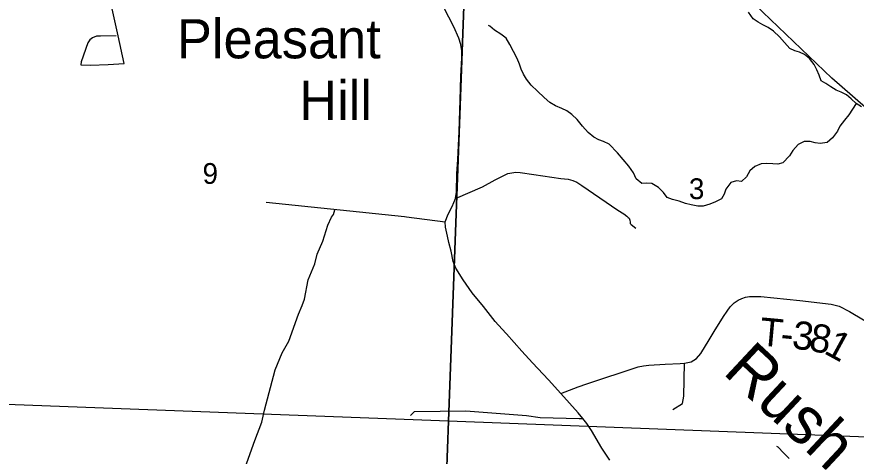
# Model space of a CAD drawing. Extents: x 0 to 34, y 0 to 22.
# Drawn here: x 4.552 to 6.245, y 15.005 to 15.891 of the extents above; entities that cross this region are included whole.
import ezdxf

# ---------------------------------------------------------------- set-up
doc = ezdxf.new("R2010")
doc.units = 0
for name, color, linetype in [('Default', 7, 'Continuous'), ('GM_X_Minor_River', 7, 'Continuous'), ('GM_X_Minor_River_Text', 7, 'Continuous'), ('GM_X_Section', 7, 'Continuous'), ('GM_X_Section_Text', 7, 'Continuous'), ('GM_X_State_Route', 7, 'Continuous'), ('GM_X_Township_Road', 7, 'Continuous'), ('GM_X_Township_Road_Text', 7, 'Continuous'), ('GM_X_Unincorporated_Text', 7, 'Continuous')]:
    doc.layers.add(name, color=color, linetype=linetype)

msp = doc.modelspace()

# ---------------------------------------------------------------- linework, layer by layer
at = {"layer": 'Default'}
for p, q in [((5.4229, 15.0756), (4.4256, 15.1132)), ((5.4229, 15.0756), (5.3878, 14.1)), ((5.3878, 14.1), (5.4229, 15.0756)), ((6.3944, 15.0386), (5.4229, 15.0756))]:
    msp.add_line(p, q, dxfattribs=at)
at = {"layer": 'GM_X_Minor_River'}
for p, q in [((6.037, 15.8876), (6.0279, 15.9006)), ((6.0472, 15.8803), (6.037, 15.8876)), ((6.0568, 15.8753), (6.0472, 15.8803)), ((5.506, 15.8725), (5.5033, 15.874)), ((5.5158, 15.8641), (5.506, 15.8725)), ((5.5282, 15.8561), (5.5158, 15.8641)), ((6.0676, 15.8699), (6.0568, 15.8753)), ((6.0785, 15.8622), (6.0676, 15.8699)), ((5.5391, 15.8485), (5.5282, 15.8561)), ((5.5467, 15.8354), (5.5391, 15.8485)), ((6.0903, 15.8512), (6.0785, 15.8622)), ((6.1005, 15.8393), (6.0903, 15.8512)), ((5.5536, 15.8211), (5.5467, 15.8354)), ((6.1112, 15.8275), (6.1005, 15.8393)), ((5.5609, 15.8073), (5.5536, 15.8211)), ((6.1212, 15.8229), (6.1112, 15.8275)), ((6.1308, 15.8201), (6.1212, 15.8229)), ((6.1408, 15.8155), (6.1308, 15.8201)), ((6.1506, 15.8071), (6.1408, 15.8155)), ((5.5658, 15.796), (5.5609, 15.8073)), ((5.5696, 15.7855), (5.5658, 15.796)), ((6.1601, 15.7952), (6.1506, 15.8071)), ((5.5737, 15.7757), (5.5696, 15.7855)), ((6.1657, 15.7847), (6.1601, 15.7952)), ((6.1702, 15.7738), (6.1657, 15.7847)), ((5.5797, 15.7656), (5.5737, 15.7757)), ((5.5896, 15.7538), (5.5797, 15.7656)), ((6.174, 15.7621), (6.1702, 15.7738)), ((6.1837, 15.7567), (6.174, 15.7621)), ((5.6021, 15.7412), (5.5896, 15.7538)), ((6.1938, 15.7502), (6.1837, 15.7567)), ((6.2046, 15.7437), (6.1938, 15.7502)), ((5.6158, 15.7284), (5.6021, 15.7412)), ((5.6268, 15.7188), (5.6158, 15.7284)), ((6.2146, 15.7395), (6.2046, 15.7437)), ((6.2251, 15.7341), (6.2146, 15.7395)), ((6.2348, 15.7256), (6.2251, 15.7341)), ((5.6388, 15.7116), (5.6268, 15.7188)), ((5.6515, 15.7066), (5.6388, 15.7116)), ((6.2446, 15.7168), (6.2298, 15.6939)), ((6.2446, 15.7168), (6.2348, 15.7256)), ((6.2555, 15.7099), (6.2446, 15.7168)), ((5.6615, 15.702), (5.6515, 15.7066)), ((5.6717, 15.694), (5.6615, 15.702)), ((5.6819, 15.684), (5.6717, 15.694)), ((5.6929, 15.671), (5.6819, 15.684)), ((6.2217, 15.683), (6.2119, 15.6705)), ((6.2298, 15.6939), (6.2217, 15.683)), ((5.7047, 15.6577), (5.6929, 15.671)), ((6.2072, 15.6605), (6.1974, 15.6472)), ((6.2119, 15.6705), (6.2072, 15.6605)), ((5.7157, 15.6485), (5.7047, 15.6577)), ((5.7257, 15.6435), (5.7157, 15.6485)), ((5.7353, 15.64), (5.7257, 15.6435)), ((6.1974, 15.6472), (6.1863, 15.6378)), ((5.7465, 15.6343), (5.7353, 15.64)), ((5.7638, 15.6173), (5.7465, 15.6343)), ((6.1282, 15.6337), (6.1172, 15.6215)), ((6.1398, 15.6401), (6.1282, 15.6337)), ((6.1524, 15.6401), (6.1398, 15.6401)), ((6.1623, 15.6374), (6.1524, 15.6401)), ((6.1726, 15.6358), (6.1623, 15.6374)), ((6.1863, 15.6378), (6.1726, 15.6358)), ((5.7752, 15.6036), (5.7638, 15.6173)), ((6.1107, 15.6111), (6.0967, 15.5969)), ((6.1172, 15.6215), (6.1107, 15.6111)), ((5.7867, 15.5903), (5.7752, 15.6036)), ((6.0534, 15.5948), (6.0406, 15.5895)), ((6.0648, 15.5952), (6.0534, 15.5948)), ((6.0766, 15.5948), (6.0648, 15.5952)), ((6.0869, 15.5943), (6.0766, 15.5948)), ((6.0967, 15.5969), (6.0869, 15.5943)), ((5.7958, 15.5769), (5.7867, 15.5903)), ((5.8015, 15.5645), (5.7958, 15.5769)), ((6.0307, 15.5808), (6.0238, 15.5684)), ((6.0406, 15.5895), (6.0307, 15.5808)), ((5.8125, 15.555), (5.8015, 15.5645)), ((6.0035, 15.5602), (5.9922, 15.5572)), ((6.0138, 15.5594), (6.0035, 15.5602)), ((6.0238, 15.5684), (6.0138, 15.5594)), ((5.8227, 15.5557), (5.8125, 15.555)), ((5.8326, 15.5548), (5.8227, 15.5557)), ((5.8462, 15.5473), (5.8326, 15.5548)), ((5.8564, 15.5369), (5.8462, 15.5473)), ((5.982, 15.5435), (5.9785, 15.5339)), ((5.9922, 15.5572), (5.982, 15.5435)), ((5.8635, 15.5269), (5.8564, 15.5369)), ((5.8743, 15.5227), (5.8635, 15.5269)), ((5.9785, 15.5339), (5.9731, 15.5242)), ((5.8877, 15.5193), (5.8743, 15.5227)), ((5.9008, 15.5151), (5.8877, 15.5193)), ((5.9123, 15.5124), (5.9008, 15.5151)), ((5.9257, 15.5094), (5.9123, 15.5124)), ((5.9363, 15.5094), (5.9257, 15.5094)), ((5.9495, 15.5132), (5.9363, 15.5094)), ((5.9612, 15.5178), (5.9495, 15.5132)), ((5.9731, 15.5242), (5.9612, 15.5178)), ((5.1865, 15.4873), (5.1906, 15.4923)), ((5.1906, 15.4923), (5.1934, 15.5018)), ((5.1796, 15.4712), (5.1865, 15.4873)), ((5.1696, 15.4387), (5.1796, 15.4712)), ((5.1576, 15.4123), (5.1696, 15.4387)), ((5.1534, 15.3928), (5.1576, 15.4123)), ((5.1396, 15.361), (5.1534, 15.3928)), ((5.1324, 15.3218), (5.1396, 15.361)), ((5.1273, 15.3091), (5.1324, 15.3218)), ((5.1204, 15.2915), (5.1273, 15.3091)), ((5.1006, 15.2372), (5.1204, 15.2915)), ((5.087, 15.2134), (5.1006, 15.2372)), ((5.0733, 15.1794), (5.087, 15.2134)), ((5.0513, 15.098), (5.0733, 15.1794)), ((5.0464, 15.0736), (5.0513, 15.098)), ((5.0323, 15.0369), (5.0464, 15.0736)), ((5.0129, 14.9819), (5.0323, 15.0369)), ((6.0877, 15.0232), (6.085, 15.0246)), ((6.0986, 15.0121), (6.0877, 15.0232)), ((6.11, 15.0003), (6.0986, 15.0121))]:
    msp.add_line(p, q, dxfattribs=at)
at = {"layer": 'GM_X_Section'}
for p, q in [((5.4597, 16.0717), (5.4229, 15.0756)), ((5.4229, 15.0756), (5.4597, 16.0717)), ((5.4229, 15.0756), (4.4256, 15.1132)), ((6.3944, 15.0386), (5.4229, 15.0756))]:
    msp.add_line(p, q, dxfattribs=at)
at = {"layer": 'GM_X_State_Route'}
for p, q in [((5.4333, 15.8712), (5.4036, 15.9288)), ((5.4433, 15.8485), (5.4333, 15.8712)), ((5.4475, 15.8354), (5.4433, 15.8485)), ((5.4496, 15.8227), (5.4475, 15.8354)), ((5.4496, 15.8088), (5.4496, 15.8227)), ((5.4478, 15.7712), (5.4496, 15.8088)), ((5.446, 15.7231), (5.4478, 15.7712)), ((5.4448, 15.6817), (5.446, 15.7231)), ((5.4439, 15.6599), (5.4448, 15.6817)), ((5.4414, 15.6036), (5.4439, 15.6599)), ((5.4398, 15.5748), (5.4414, 15.6036)), ((5.4391, 15.5373), (5.4398, 15.5748)), ((5.4302, 15.5087), (5.4371, 15.5248)), ((5.4371, 15.5248), (5.4391, 15.5373)), ((5.4223, 15.4933), (5.4302, 15.5087)), ((5.4157, 15.4778), (5.4223, 15.4933)), ((5.4164, 15.4673), (5.4157, 15.4778)), ((5.4204, 15.4489), (5.4164, 15.4673)), ((5.4233, 15.4361), (5.4204, 15.4489)), ((5.4279, 15.4186), (5.4233, 15.4361)), ((5.4322, 15.3976), (5.4279, 15.4186)), ((5.4376, 15.384), (5.4322, 15.3976)), ((5.4521, 15.3611), (5.4376, 15.384)), ((5.4707, 15.3346), (5.4521, 15.3611)), ((5.4936, 15.3069), (5.4707, 15.3346)), ((5.5171, 15.2768), (5.4936, 15.3069)), ((5.5383, 15.2533), (5.5171, 15.2768)), ((5.5397, 15.2518), (5.5383, 15.2533)), ((5.5707, 15.2166), (5.5397, 15.2518)), ((5.5921, 15.1931), (5.5707, 15.2166)), ((5.6243, 15.1591), (5.5921, 15.1931)), ((5.649, 15.1316), (5.6243, 15.1591)), ((5.6839, 15.0925), (5.649, 15.1316)), ((5.6935, 15.0809), (5.6839, 15.0925)), ((5.7015, 15.0708), (5.6935, 15.0809)), ((5.7109, 15.057), (5.7015, 15.0708)), ((5.7323, 15.021), (5.7109, 15.057)), ((5.7484, 14.9968), (5.7323, 15.021))]:
    msp.add_line(p, q, dxfattribs=at)
at = {"layer": 'GM_X_Township_Road'}
for p, q in [((6.1959, 15.7676), (6.0071, 15.9482)), ((4.7565, 15.8529), (4.7405, 15.9263)), ((4.7044, 15.8488), (4.6992, 15.8451)), ((4.713, 15.852), (4.7044, 15.8488)), ((4.7208, 15.8524), (4.713, 15.852)), ((4.7526, 15.8532), (4.7208, 15.8524)), ((4.7684, 15.7974), (4.7565, 15.8529)), ((4.6954, 15.8386), (4.6819, 15.8006)), ((4.6992, 15.8451), (4.6954, 15.8386)), ((4.6819, 15.8006), (4.6814, 15.7942)), ((4.7363, 15.795), (4.7684, 15.7974)), ((4.6814, 15.7942), (4.701, 15.794)), ((4.701, 15.794), (4.7363, 15.795)), ((6.2869, 15.6882), (6.1959, 15.7676)), ((5.5422, 15.5752), (5.5588, 15.578)), ((5.5588, 15.578), (5.5675, 15.5773)), ((5.5675, 15.5773), (5.5946, 15.5732)), ((5.4914, 15.5485), (5.5166, 15.5628)), ((5.5166, 15.5628), (5.5422, 15.5752)), ((5.5946, 15.5732), (5.6495, 15.5653)), ((5.6495, 15.5653), (5.6642, 15.5639)), ((5.6642, 15.5639), (5.6734, 15.5614)), ((5.6734, 15.5614), (5.6814, 15.5578)), ((5.4371, 15.5248), (5.4914, 15.5485)), ((5.6814, 15.5578), (5.6915, 15.551)), ((5.6915, 15.551), (5.7643, 15.5014)), ((5.0547, 15.5177), (5.3337, 15.4884)), ((5.7643, 15.5014), (5.7761, 15.4937)), ((5.7761, 15.4937), (5.7824, 15.4892)), ((5.3337, 15.4884), (5.3378, 15.488)), ((5.3378, 15.488), (5.4157, 15.4778)), ((5.7824, 15.4892), (5.7853, 15.4864)), ((5.7853, 15.4864), (5.7868, 15.485)), ((5.7868, 15.485), (5.7882, 15.481)), ((5.7882, 15.481), (5.789, 15.4769)), ((5.789, 15.4769), (5.7894, 15.4744)), ((5.7894, 15.4744), (5.7909, 15.4727)), ((5.7909, 15.4727), (5.8007, 15.465)), ((6.007, 15.3201), (6.0143, 15.3233)), ((6.0143, 15.3233), (6.0217, 15.3259)), ((6.0217, 15.3259), (6.0299, 15.3271)), ((6.0299, 15.3271), (6.0375, 15.3274)), ((6.0375, 15.3274), (6.0527, 15.3271)), ((6.0527, 15.3271), (6.131, 15.3194)), ((5.9846, 15.2979), (5.9906, 15.3062)), ((5.9906, 15.3062), (5.9986, 15.3141)), ((5.9986, 15.3141), (6.007, 15.3201)), ((6.131, 15.3194), (6.1944, 15.3118)), ((6.1944, 15.3118), (6.2106, 15.3074)), ((6.2106, 15.3074), (6.2316, 15.2969)), ((5.9775, 15.2867), (5.9846, 15.2979)), ((6.2316, 15.2969), (6.3003, 15.256)), ((5.9585, 15.2563), (5.9775, 15.2867)), ((5.9482, 15.2395), (5.9585, 15.2563)), ((5.9317, 15.2124), (5.9482, 15.2395)), ((5.9226, 15.2018), (5.9317, 15.2124)), ((5.805, 15.1852), (5.8162, 15.1876)), ((5.8162, 15.1876), (5.8266, 15.1888)), ((5.8266, 15.1888), (5.8596, 15.1905)), ((5.8596, 15.1905), (5.8901, 15.1919)), ((5.8901, 15.1919), (5.8987, 15.1928)), ((5.8973, 15.126), (5.8987, 15.1928)), ((5.8987, 15.1928), (5.9121, 15.1955)), ((5.9121, 15.1955), (5.9226, 15.2018)), ((5.7017, 15.1508), (5.805, 15.1852)), ((5.649, 15.1316), (5.6839, 15.1447)), ((5.6839, 15.1447), (5.7017, 15.1508)), ((5.8949, 15.1112), (5.8973, 15.126)), ((5.8754, 15.0995), (5.8949, 15.1112)), ((5.3463, 15.0874), (5.3542, 15.0951)), ((5.3542, 15.0951), (5.4575, 15.0963)), ((5.4575, 15.0963), (5.58, 15.0873)), ((5.58, 15.0873), (5.6074, 15.0831)), ((5.6074, 15.0831), (5.6864, 15.0811)), ((5.6864, 15.0811), (5.6935, 15.0809))]:
    msp.add_line(p, q, dxfattribs=at)

# ---------------------------------------------------------------- texts
at = {"layer": 'GM_X_Minor_River_Text'}
msp.add_text('Rush', height=0.0947, rotation=316.972, dxfattribs=at).set_placement((5.9737, 15.173))
at = {"layer": 'GM_X_Section_Text'}
for s, p in [('9', (4.9267, 15.5544)), ('3', (5.9076, 15.5236))]:
    msp.add_text(s, height=0.0419, rotation=0, dxfattribs=at).set_placement(p)
at = {"layer": 'GM_X_Township_Road_Text'}
for s, rotation, p in [('T', 354.7602, (6.0486, 15.2286)), ('3', 353.2455, (6.1138, 15.2225)), ('8', 349.381, (6.1475, 15.2185)), ('1', 331.3958, (6.1775, 15.2137)), ('-', 354.3865, (6.0908, 15.2248))]:
    msp.add_text(s, height=0.0568, rotation=rotation, dxfattribs=at).set_placement(p)
at = {"layer": 'GM_X_Unincorporated_Text'}
for s, p in [('Pleasant', (4.8751, 15.8076)), ('Hill', (5.1217, 15.6835))]:
    msp.add_text(s, height=0.07898, rotation=0, dxfattribs=at).set_placement(p)

doc.saveas('drawing.dxf')
